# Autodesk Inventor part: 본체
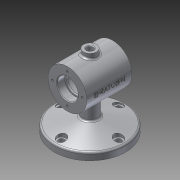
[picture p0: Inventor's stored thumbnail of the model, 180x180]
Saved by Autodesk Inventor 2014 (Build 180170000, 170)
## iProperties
Created: 2018-12
Part Number: 본체
Material: 알루미늄 6061
Document SubType Name: Modeling
Designer: oa-51
Density: 2.71 g/cm^3
Appearance: 알루미늄 - 평지
Mass: 687.765 g
Surface Area: 556.058 cm^2
Volume: 253.788 cm^3
Author: oa-51
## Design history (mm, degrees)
sketch "스케치1"
  geometry: C1 r 55 at (0, 0); 1 further point
  constraints: 1 centre point, 1 coincident
  dimensions: "d0" = 110 diameter of C1
extrude "돌출1" new body sketch "스케치1" distance "d1" = 11; taper "d2" = 0 deg
sketch "스케치2"
  geometry: L1 (55, 0)-(55, 11) reference; L2 (-55, 0)-(-55, 11) reference; L3 (-55, 11)-(0, 25.737); L4 (55, 11)-(0, 25.737); L5 (55, 11)-(-55, 11) reference; L6 (0, 25.737)-(0, 11); L7 (-55, 11)-(0, 11); 1 further point
  constraints: 8 end point, 1 collinear, 1 midpoint
  dimensions: "d4" = 75 deg angle of L4 L1; "d5" = 75 deg angle of L3 L2
revolve "회전1" sketch "스케치2" stored, may be unused: angle "d6" = 90 deg
sketch "스케치4"
  geometry: L1 (-46.167, 75)-(46.167, 75); L2 (-35, 75)-(-35, 105); L3 (-35, 105)-(35, 105); L4 (35, 105)-(35, 75); 3 further points
  constraints: 8 end point, 3 perpendicular, 2 midpoint, 2 point on line, 2 vertical alignment, 1 horizontal
  dimensions: "d7" = 75 distance from line of L1 point (0, 0); "d8" = 60 diameter of L3 L1; "d9" = 70 distance of L2.end L3.end
revolve "회전2" sketch "스케치4" stored, may be unused: angle "d10" = 90 deg
sketch "스케치5" dims "d11" = 46
  geometry: C1 r 30 at (0, 0) reference; 6 further points
  constraints: 2 vertical alignment, 1 coincident, 7 other
  dimensions: "d14" = 360 deg dimension on C1.centre point (0, 23) (derived)
hole "구멍1" sketch "스케치5" at (0, 23), (-23, 0), (0, -23), (23, 0) diameter "d16" = 3.242; stored, may be unused: countersink angle "d20" = 90 deg, drill point angle "d22" = 118 deg; dims "d17" = 8, "d18" = 4, "d19" = 2, "d21" = 10
sketch "스케치6"
  geometry: L1 (-35, 45)-(-35, 105) reference; L2 (35, 45)-(35, 105) reference; L3 (-35, 75)-(35, 75); L4 (-35, 91)-(-23, 91); L5 (-23, 91)-(-23, 89); L6 (-23, 89)-(-20, 89); L7 (-20, 89)-(-20, 100); L8 (-20, 100)-(20, 100); L9 (20, 100)-(20, 89); L10 (20, 89)-(23, 89); L11 (23, 89)-(23, 91); L12 (23, 91)-(35, 91); L13 (-35, 91)-(-35, 75); L14 (35, 91)-(35, 75); 2 further points
  constraints: 24 end point, 7 parallel, 5 collinear, 3 midpoint, 2 perpendicular, 2 point on line, 1 horizontal, 1 vertical alignment
  dimensions: "d23" = 32 diameter of L4 L3; "d24" = 28 diameter of L6 L3; "d25" = 50 diameter of L8 L3; "d26" = 12 distance of L4.start L4.end; "d27" = 40 distance of L7.end L8.end
revolve "회전3" sketch "스케치6" stored, may be unused: angle "d28" = 90 deg
fillet "모깎기1" dims "d29" = 3, "d30" = 0.3
node "작업 평면2"
sketch "스케치7"
  geometry: C1 r 10 at (0, 0); 1 further point
  constraints: 1 centre point, 1 coincident
  dimensions: "d32" = 20 diameter of C1
extrude "돌출2" join sketch "스케치7" stored distance "d33" = 10; taper "d34" = 0 deg
sketch "스케치8"
  geometry: C1 r 10 at (0, 0) reference; C2 r 5 at (0, 0)
  constraints: 1 centre point, 1 coincident
  dimensions: "d35" = 10 diameter of C2
extrude "돌출3" cut sketch "스케치8" stored distance "d36" = 10; taper "d37" = 0 deg
chamfer "모따기1" distance "d38" = 1; stored, may be unused: second distance "d39" = 2, angle "d40" = 45 deg
chamfer "모따기2" distance "d41" = 1; stored, may be unused: second distance "d42" = 2, angle "d43" = 45 deg
node "작업 평면3"
sketch "스케치9"
  geometry: C1 r 12 at (0, 0); 1 further point
  constraints: 1 centre point, 1 coincident
  dimensions: "d45" = 24 diameter of C1
extrude "돌출4" join sketch "스케치9" stored distance "d46" = 10; taper "d47" = 0 deg
sketch "스케치10" dims "d48" = 88
  geometry: 6 further points
  constraints: 2 vertical alignment, 1 coincident, 7 other
  dimensions: "d51" = 360 deg dimension on point (0, 0) point (0, 44) (derived)
sketch "스케치11" dims "d53" = 88
  geometry: C1 r 55 at (0, 0) reference; 5 further points
  constraints: 2 horizontal alignment, 1 coincident, 7 other
  dimensions: "d56" = 360 deg dimension on C1.centre point (44, 0) (derived)
hole "구멍2" sketch "스케치11" at (-44, 0), (0, 44), (0, -44), (44, 0) diameter "d58" = 9; stored, may be unused: countersink angle "d62" = 90 deg, drill point angle "d64" = 0 deg; dims "d59" = 8, "d60" = 14, "d61" = 2, "d63" = 10
hole "구멍3" sketch "스케치10" diameter "d65" = 14; stored, may be unused: countersink angle "d69" = 90 deg, drill point angle "d71" = 0 deg; dims "d66" = 8, "d67" = 14, "d68" = 2, "d70" = 8
fillet "모깎기2" dims "d72" = 3
node "작업 평면4"
sketch "스케치12"
  geometry: L1 (-35, 30)-(35, 30) reference; 2 further points
  constraints: 1 vertical alignment, 1 other
  dimensions: "d73" = 30 distance from line of point (0, 0) L1
feature "엠보싱1" sketch "스케치12" dims "d74" = 0.5, "d75" = 0
chamfer "모따기3" distance "d76" = 1; stored, may be unused: second distance "d77" = 2, angle "d78" = 45 deg
node "솔리드1"
mirror "대칭1"
node "작업 평면1"
other parameters: "d31" = -112, "d44" = -18
